(* Logix 5000 project; controller V16_L55_Blank vendor 1 type 14 code 51 rev 16.2; software revision 16.04; part 4 of 5 *)
(* AOI69EAFCMeterLinearGas, continued *)

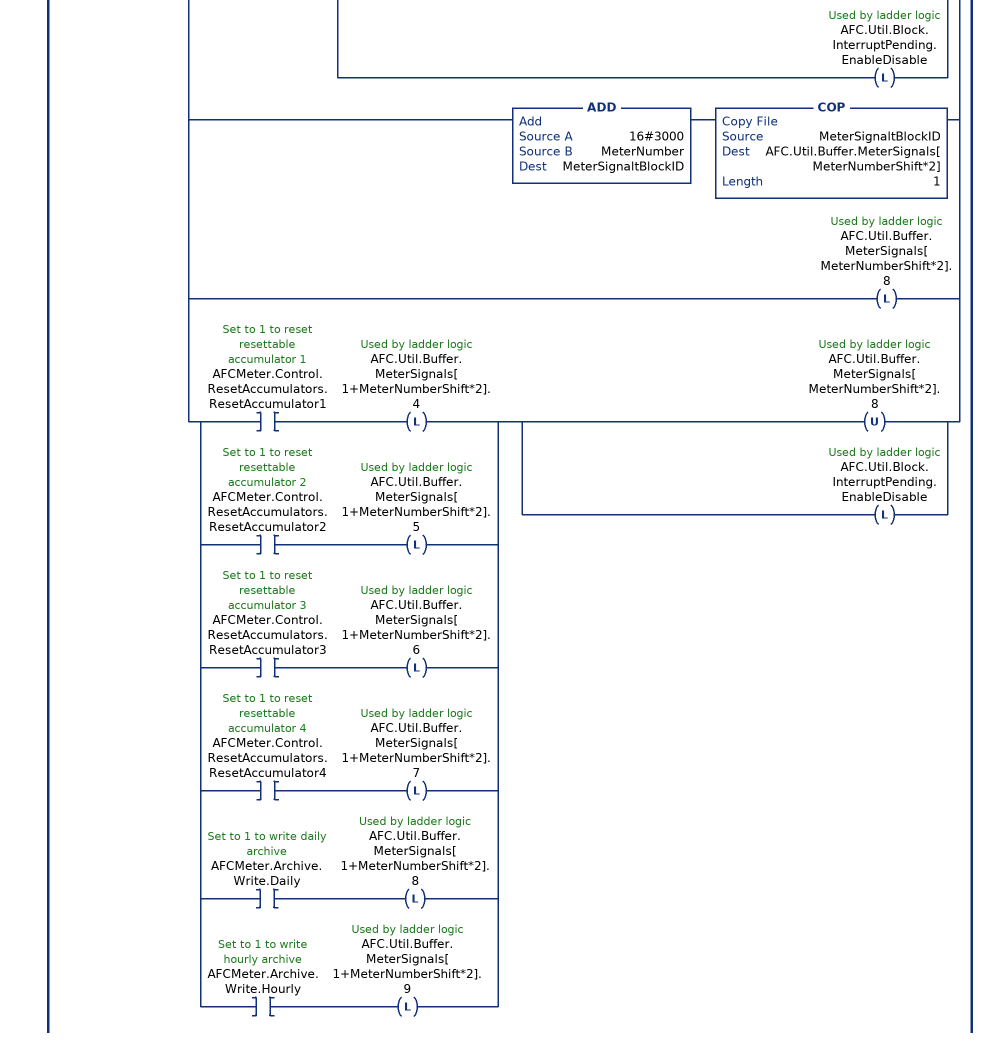
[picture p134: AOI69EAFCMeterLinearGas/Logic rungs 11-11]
   // Meter Enable.
   // Meter Disable.
   // Stream Select.
   // Stream Enable.
   // Stream Disable.
   // Set pending bit if not set this interrupt cycle.
   11: XIO(AFC.Util.Block.InterruptComplete.EnableDisable)[LIM(1,AFCMeter.Control.Stream.Selected,16) CPT(StreamEnableBitPosition,2**(AFCMeter.Control.Stream.Selected-1)) ,[XIC(AFCMeter.Control.Meter.Enable) MVM(16#FFFF,MeterNumberBitPostition,AFC.Util.Buffer.MeterEnableDisable[1]) MVM(16#0000,MeterNumberBitPostition,AFC.Util.Buffer.MeterEnableDisable[3]) ,XIC(AFCMeter.Control.Meter.Disable) MVM(16#FFFF,MeterNumberBitPostition,AFC.Util.Buffer.MeterEnableDisable[3]) MVM(16#0000,MeterNumberBitPostition,AFC.Util.Buffer.MeterEnableDisable[1]) ] OTL(AFC.Util.Block.InterruptPending.EnableDisable) ,[ADD(16#CC00,MeterNumber,StreamEnableBlockID) COP(StreamEnableBlockID,AFC.Util.Buffer.StreamEnable[MeterNumberShift*3],1) ,XIO(AFCMeter.Control.Stream.EnableSelected) OTL(AFC.Util.Buffer.StreamEnable[MeterNumberShift*3].8) ,XIC(AFCMeter.Control.Stream.EnableSelected) [OTU(AFC.Util.Buffer.StreamEnable[MeterNumberShift*3].8) ,COP(StreamEnableBitPosition,AFC.Util.Buffer.StreamEnable[1+MeterNumberShift*3],1) ,OTL(AFC.Util.Block.InterruptPending.EnableDisable) ] ] ,[ADD(16#C800,MeterNumber,StreamDisableBlockID) COP(StreamDisableBlockID,AFC.Util.Buffer.StreamDisable[MeterNumberShift*3],1) ,XIO(AFCMeter.Control.Stream.DisableSelected) OTL(AFC.Util.Buffer.StreamDisable[MeterNumberShift*3].8) ,XIC(AFCMeter.Control.Stream.DisableSelected) [OTU(AFC.Util.Buffer.StreamDisable[MeterNumberShift*3].8) ,COP(StreamEnableBitPosition,AFC.Util.Buffer.StreamDisable[1+MeterNumberShift*3],1) ,OTL(AFC.Util.Block.InterruptPending.EnableDisable) ] ] ,[ADD(16#3C00,MeterNumber,StreamSelectBlockID) COP(StreamSelectBlockID,AFC.Util.Buffer.StreamSelect[MeterNumberShift*2],1) ,XIO(AFCMeter.Control.Stream.SetSelectedToActive) OTL(AFC.Util.Buffer.StreamSelect[MeterNumberShift*2].8) ,XIC(AFCMeter.Control.Stream.SetSelectedToActive) [OTU(AFC.Util.Buffer.StreamSelect[MeterNumberShift*2].8) ,MOV(AFCMeter.Control.Stream.Selected,AFC.Util.Buffer.StreamSelect[1+MeterNumberShift*2]) ,OTL(AFC.Util.Block.InterruptPending.EnableDisable) ] ] ,[ADD(16#3000,MeterNumber,MeterSignaltBlockID) COP(MeterSignaltBlockID,AFC.Util.Buffer.MeterSignals[MeterNumberShift*2],1) ,OTL(AFC.Util.Buffer.MeterSignals[MeterNumberShift*2].8) ,[XIC(AFCMeter.Control.ResetAccumulators.ResetAccumulator1) OTL(AFC.Util.Buffer.MeterSignals[1+MeterNumberShift*2].4) ,XIC(AFCMeter.Control.ResetAccumulators.ResetAccumulator2) OTL(AFC.Util.Buffer.MeterSignals[1+MeterNumberShift*2].5) ,XIC(AFCMeter.Control.ResetAccumulators.ResetAccumulator3) OTL(AFC.Util.Buffer.MeterSignals[1+MeterNumberShift*2].6) ,XIC(AFCMeter.Control.ResetAccumulators.ResetAccumulator4) OTL(AFC.Util.Buffer.MeterSignals[1+MeterNumberShift*2].7) ,XIC(AFCMeter.Archive.Write.Daily) OTL(AFC.Util.Buffer.MeterSignals[1+MeterNumberShift*2].8) ,XIC(AFCMeter.Archive.Write.Hourly) OTL(AFC.Util.Buffer.MeterSignals[1+MeterNumberShift*2].9) ] [OTU(AFC.Util.Buffer.MeterSignals[MeterNumberShift*2].8) ,OTL(AFC.Util.Block.InterruptPending.EnableDisable) ] ] ];
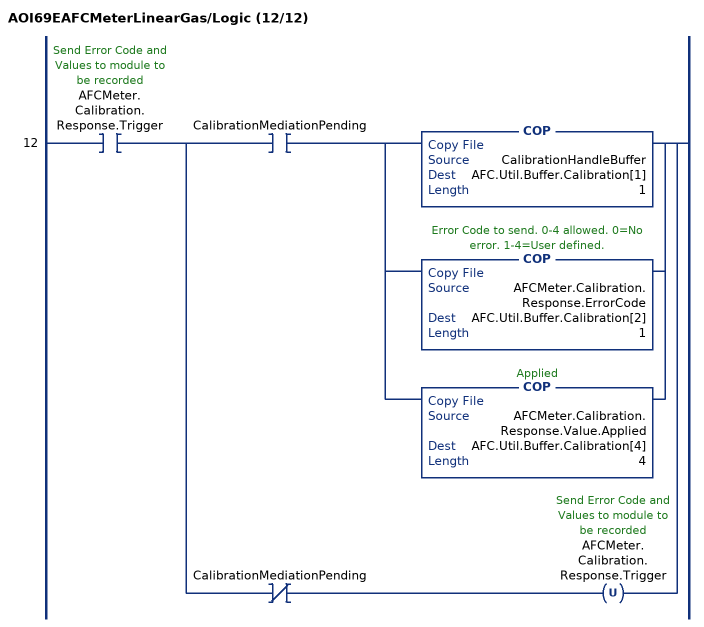
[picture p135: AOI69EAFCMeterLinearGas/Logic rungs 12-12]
   12: XIC(AFCMeter.Calibration.Response.Trigger)[XIC(CalibrationMediationPending) [COP(CalibrationHandleBuffer,AFC.Util.Buffer.Calibration[1],1) ,COP(AFCMeter.Calibration.Response.ErrorCode,AFC.Util.Buffer.Calibration[2],1) ,COP(AFCMeter.Calibration.Response.Value.Applied,AFC.Util.Buffer.Calibration[4],4) ] ,XIO(CalibrationMediationPending) OTU(AFCMeter.Calibration.Response.Trigger) ];
END_ROUTINE

ROUTINE Prescan   (* ladder *)
// Prescan
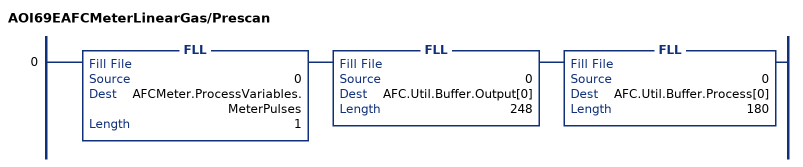
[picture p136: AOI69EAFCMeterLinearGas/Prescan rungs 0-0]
   0: FLL(0,AFCMeter.ProcessVariables.MeterPulses,1)FLL(0,AFC.Util.Buffer.Output[0],248)FLL(0,AFC.Util.Buffer.Process[0],180);
END_ROUTINE
END_ADD_ON_INSTRUCTION

ADD_ON_INSTRUCTION AOI69EAFCMeterLinearLiquid   (* revision 1.5, ExecutePrescan *)
// Add-On instruction for the MVI69E-AFC.
// Linear Liquid Meter.
// Revision note:
// Updated  BackplaneReturn Tag name from ProcessInputs to Standard
// and ComponentAnalysis to Extended
// Help:
// Compatible with version 4.04 of MVI69E-AFC firmware or higher.
// v1.1: Comp Analysis Return fix
// v1.2: Addition of default process input backplane return data mapping.
// v1.3: Changed Prescan FLL instruction length from 240 words to 180 for proccess inputs. This stopped mismatch issue.
// v1.3: Made correlation changes between the Module Archive Default UDTs and the AOI Archive Default UDTs.
// v1.4: Made changes to the ModbusGatewayConfig UDT StartRegister Tag Data Type from INT to DINT.
// v1.5: Updated Tags names AFCMeterXXYYYYYY.BackPlaneReturn.ProcessInputs to
// AFCMeterXXYYYYYY.BackPlaneReturn.Standard and
// AFCMeterXXYYYYYY.BackPlaneReturn.ComponentAnalysis
//  to AFCMeterXXYYYYYY.BackPlaneReturn.Extended.
VAR_IN_OUT
   ConnectionInput : INT[248]; {required}
   AFC : AFCEModuleDef; {required}
   AFCMeter : AFCEMeterLinearLiquid; {required}
END_VAR
VAR_INPUT
   MeterNumber : SINT; {required}   // Meter Number Set to a number between 1 and 12
END_VAR
VAR
   StreamSelectedShift : DINT;
   StreamSelectBuffer : INT;
   EnabledStatusBuffer : INT;
   StreamSelectBlockID : DINT;
   StreamNumberShift : DINT;
   StreamErrorBuffer : DINT;
   StreamEnableBlockID : DINT;
   StreamEnableBitPosition : DINT;
   StreamDisableBlockID : DINT;
   ResetOnce : BOOL;
   ProfileBuffer : SINT[2];
   ProcessInputBlockID : DINT;
   AnalysisGroupBitPosition : INT;
   AnalysisErrorBuffer : INT;
   ProcessAlarmShifter : DINT;
   ProcessAlarmHolder : DINT;
   ProcessAlarmBuffer : DINT;
   MeterSignaltBlockID : DINT;
   MeterNumberShift : DINT;
   MeterNumberBitPostition : DINT;
   Inputbuffer : INT[248];
   CalibrationMeterNumberBuffer : DINT;
   CalibrationMediationPending : BOOL;
   CalibrationInputScalingIndex : DINT;
   CalibrationHandleBuffer : DINT;
   ArchiveStream : DINT;
   ArchiveMeterStatusRaw : DINT;
   ArchiveMeterStatusActiveStream : DINT;
   ArchiveCompleteBitCheck : DINT;
   ArchiveBlockID : DINT;
   AnalysisGroupShift : DINT;
   AnalysisCompleteBitCheck : DINT;
   AnalysisBufferOffset : DINT;
   AFCStopped : BOOL;
   AFCInputDataAvailable : BOOL;
   AnalysisBlockID : DINT;
END_VAR

ROUTINE Logic   (* ladder *)
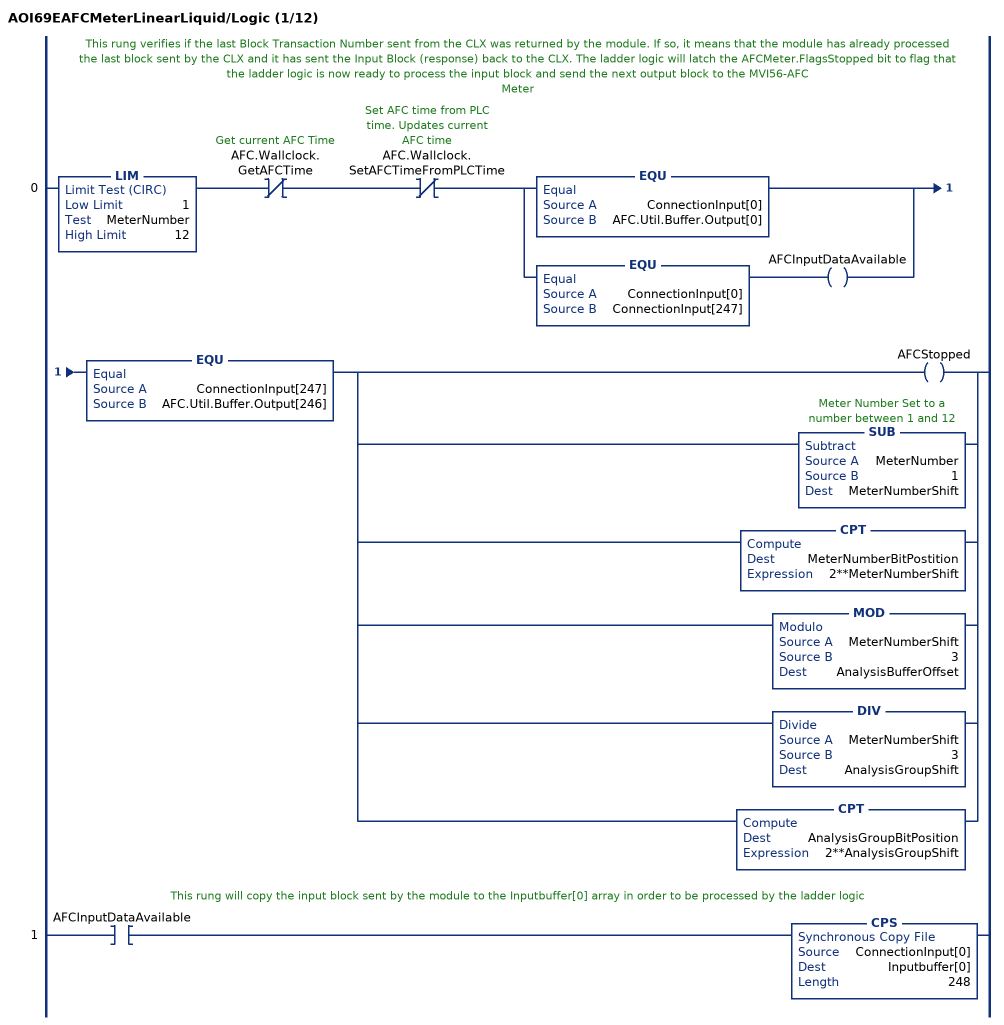
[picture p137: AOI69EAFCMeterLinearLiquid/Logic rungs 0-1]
   // This rung verifies if the last Block Transaction Number sent from the CLX was returned by the module. If so, it means that the module has already processed the last block sent by the CLX and it has sent the Input Block (response) back to the CLX. The ladder logic will latch the AFCMeter.FlagsStopped bit to flag that the ladder logic is now ready to process the input block and send the next output block to the MVI56-AFC
   // Meter
   0: LIM(1,MeterNumber,12)XIO(AFC.Wallclock.GetAFCTime)XIO(AFC.Wallclock.SetAFCTimeFromPLCTime)[EQU(ConnectionInput[0],AFC.Util.Buffer.Output[0]) ,EQU(ConnectionInput[0],ConnectionInput[247]) OTE(AFCInputDataAvailable) ]EQU(ConnectionInput[247],AFC.Util.Buffer.Output[246])[OTE(AFCStopped) ,SUB(MeterNumber,1,MeterNumberShift) ,CPT(MeterNumberBitPostition,2**MeterNumberShift) ,MOD(MeterNumberShift,3,AnalysisBufferOffset) ,DIV(MeterNumberShift,3,AnalysisGroupShift) ,CPT(AnalysisGroupBitPosition,2**AnalysisGroupShift) ];
   // This rung will copy the input block sent by the module to the Inputbuffer[0] array in order to be processed by the ladder logic
   1: XIC(AFCInputDataAvailable)CPS(ConnectionInput[0],Inputbuffer[0],248);
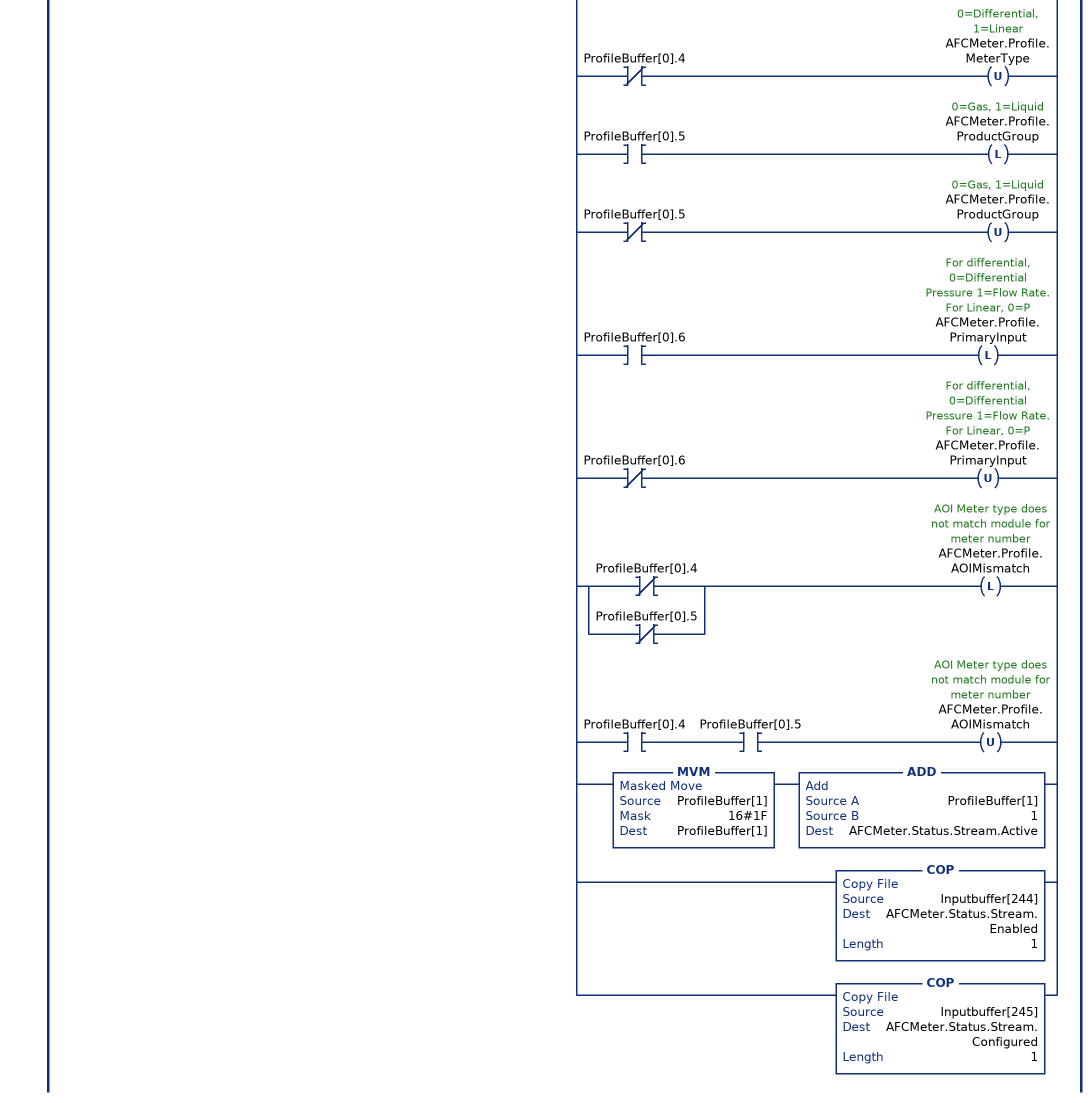
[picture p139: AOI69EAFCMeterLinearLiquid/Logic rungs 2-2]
   // Read process input backplane return and
   // meter profile (when block ID matches meter number).
   2: XIC(AFCInputDataAvailable)LIM(1,Inputbuffer[0],12)[COP(Inputbuffer[3+MeterNumberShift*15],AFCMeter.BackPlaneReturn.StandardRaw[0],14) ,COP(AFCMeter.BackPlaneReturn.StandardRaw[0],AFCMeter.BackPlaneReturn.StandardDefault,1) ,COP(Inputbuffer[246],AFC.SiteStatus,1) ,EQU(Inputbuffer[0],MeterNumber) [COP(Inputbuffer[243],ProfileBuffer[0],2) ,[XIC(ProfileBuffer[0].0) OTL(AFCMeter.Status.Meter.EnableAlarm) ,XIO(ProfileBuffer[0].0) OTU(AFCMeter.Status.Meter.EnableAlarm) ] ,[XIC(ProfileBuffer[0].1) OTL(AFCMeter.Status.Meter.Enabled) ,XIO(ProfileBuffer[0].1) OTU(AFCMeter.Status.Meter.Enabled) ] ,[[XIC(ProfileBuffer[0].4) OTL(AFCMeter.Profile.MeterType) ,XIO(ProfileBuffer[0].4) OTU(AFCMeter.Profile.MeterType) ] ,[XIC(ProfileBuffer[0].5) OTL(AFCMeter.Profile.ProductGroup) ,XIO(ProfileBuffer[0].5) OTU(AFCMeter.Profile.ProductGroup) ] ,[XIC(ProfileBuffer[0].6) OTL(AFCMeter.Profile.PrimaryInput) ,XIO(ProfileBuffer[0].6) OTU(AFCMeter.Profile.PrimaryInput) ] ] ,[[XIO(ProfileBuffer[0].4) ,XIO(ProfileBuffer[0].5) ] OTL(AFCMeter.Profile.AOIMismatch) ,XIC(ProfileBuffer[0].4) XIC(ProfileBuffer[0].5) OTU(AFCMeter.Profile.AOIMismatch) ] ,MVM(ProfileBuffer[1],16#1F,ProfileBuffer[1]) ADD(ProfileBuffer[1],1,AFCMeter.Status.Stream.Active) ,COP(Inputbuffer[244],AFCMeter.Status.Stream.Enabled,1) ,COP(Inputbuffer[245],AFCMeter.Status.Stream.Configured,1) ] ];
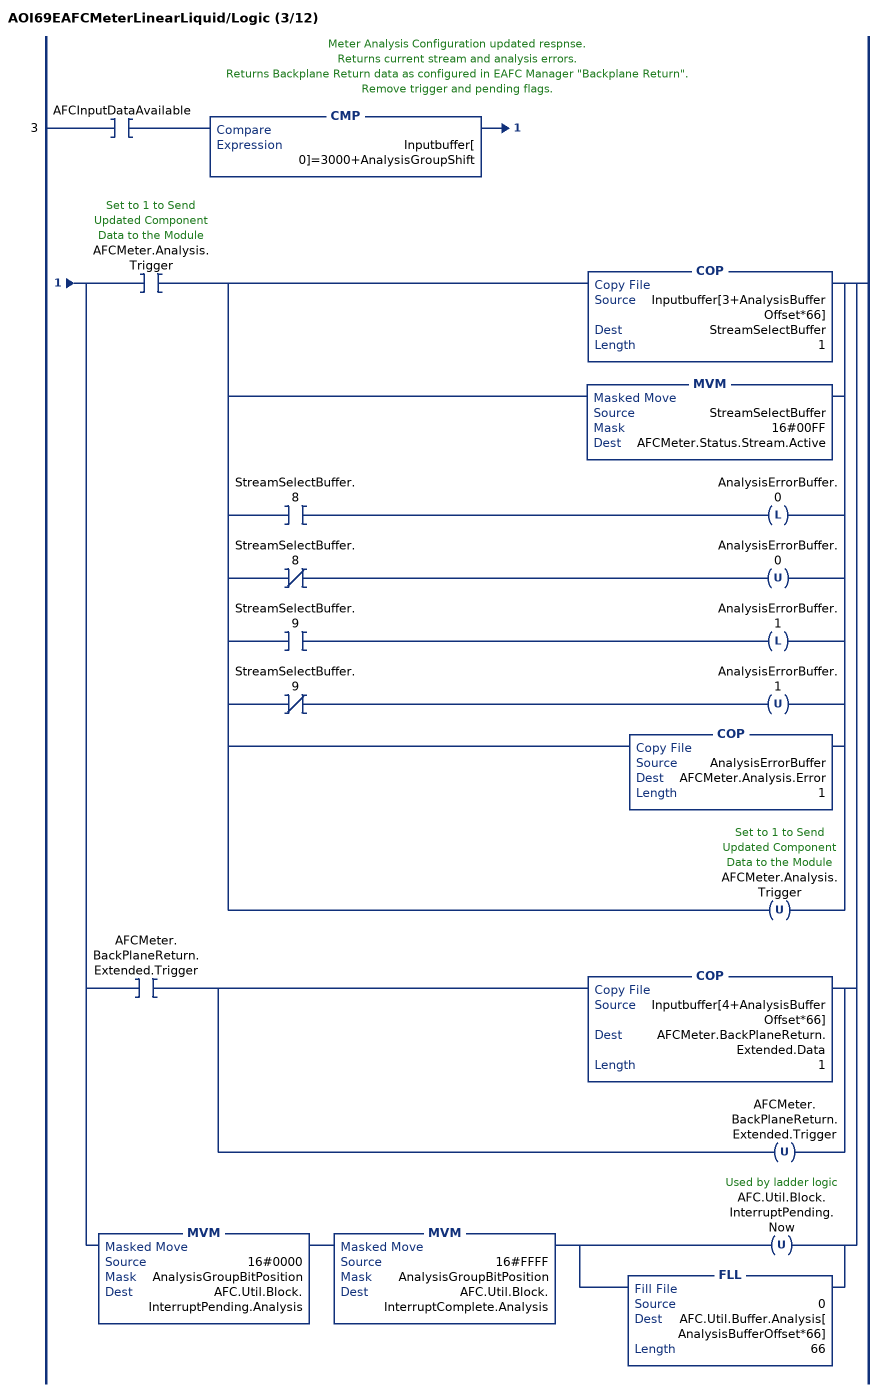
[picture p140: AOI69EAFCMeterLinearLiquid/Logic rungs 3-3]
   // Meter Analysis Configuration updated respnse.
   // Returns current stream and analysis errors.
   // Returns Backplane Return data as configured in EAFC Manager "Backplane Return".
   // Remove trigger and pending flags.
   3: XIC(AFCInputDataAvailable)CMP(Inputbuffer[0]=3000+AnalysisGroupShift)[XIC(AFCMeter.Analysis.Trigger) [COP(Inputbuffer[3+AnalysisBufferOffset*66],StreamSelectBuffer,1) ,MVM(StreamSelectBuffer,16#00FF,AFCMeter.Status.Stream.Active) ,[XIC(StreamSelectBuffer.8) OTL(AnalysisErrorBuffer.0) ,XIO(StreamSelectBuffer.8) OTU(AnalysisErrorBuffer.0) ] ,[XIC(StreamSelectBuffer.9) OTL(AnalysisErrorBuffer.1) ,XIO(StreamSelectBuffer.9) OTU(AnalysisErrorBuffer.1) ] ,COP(AnalysisErrorBuffer,AFCMeter.Analysis.Error,1) ,OTU(AFCMeter.Analysis.Trigger) ] ,XIC(AFCMeter.BackPlaneReturn.Extended.Trigger) [COP(Inputbuffer[4+AnalysisBufferOffset*66],AFCMeter.BackPlaneReturn.Extended.Data,1) ,OTU(AFCMeter.BackPlaneReturn.Extended.Trigger) ] ,MVM(16#0000,AnalysisGroupBitPosition,AFC.Util.Block.InterruptPending.Analysis) MVM(16#FFFF,AnalysisGroupBitPosition,AFC.Util.Block.InterruptComplete.Analysis) [OTU(AFC.Util.Block.InterruptPending.Now) ,FLL(0,AFC.Util.Buffer.Analysis[AnalysisBufferOffset*66],66) ] ];
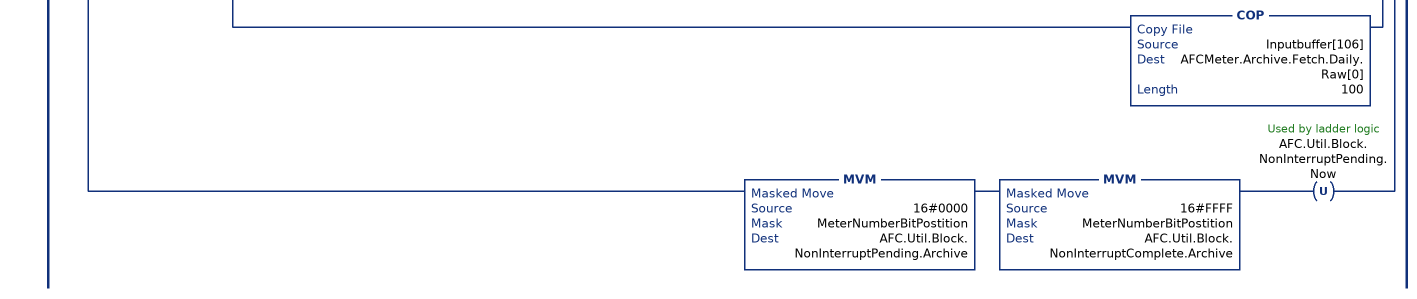
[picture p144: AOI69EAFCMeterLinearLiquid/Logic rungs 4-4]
   // Archive Fetch to default and raw UDT's.
   // Get archive alarms.
   // Remove trigger and pending flags.
   4: XIC(AFCInputDataAvailable)CMP(Inputbuffer[0]=6000+MeterNumberShift)[XIC(AFCMeter.Archive.Fetch.Hourly.Trigger) [OTU(AFCMeter.Archive.Fetch.Hourly.Trigger) ,[[XIC(Inputbuffer[3].0) OTL(AFCMeter.Archive.Fetch.Hourly.Error.ArchiveSelectionInvalid) ,XIO(Inputbuffer[3].0) OTU(AFCMeter.Archive.Fetch.Hourly.Error.ArchiveSelectionInvalid) ] ,[XIC(Inputbuffer[3].1) OTL(AFCMeter.Archive.Fetch.Hourly.Error.AgeOutsideSize) ,XIO(Inputbuffer[3].1) OTU(AFCMeter.Archive.Fetch.Hourly.Error.AgeOutsideSize) ] ,[XIC(Inputbuffer[3].2) OTL(AFCMeter.Archive.Fetch.Hourly.Error.ArchiveNeverWritten) ,XIO(Inputbuffer[3].2) OTU(AFCMeter.Archive.Fetch.Hourly.Error.ArchiveNeverWritten) ] ] ,COP(Inputbuffer[4],AFCMeter.Archive.Fetch.Hourly.Default.ClosingTimestamp,1) ,COP(Inputbuffer[6],AFCMeter.Archive.Fetch.Hourly.Default.CumulativeActiveStreams,1) ,COP(Inputbuffer[7],ArchiveMeterStatusActiveStream,1) [MVM(ArchiveMeterStatusActiveStream,16#0000000F,ArchiveStream) ADD(ArchiveStream,1,AFCMeter.Archive.Fetch.Hourly.Default.CurrentActiveStream) ,MVM(ArchiveMeterStatusActiveStream,16#0000FF00,ArchiveMeterStatusRaw) DIV(ArchiveMeterStatusRaw,256,ArchiveMeterStatusRaw) COP(ArchiveMeterStatusRaw,AFCMeter.Archive.Fetch.Hourly.Default.MeterStatus,1) ] ,COP(Inputbuffer[8],AFCMeter.Archive.Fetch.Hourly.Default.FlowingPeriod,48) ,COP(Inputbuffer[4],AFCMeter.Archive.Fetch.Hourly.Raw[0],100) ] ,XIC(AFCMeter.Archive.Fetch.Daily.Trigger) [OTU(AFCMeter.Archive.Fetch.Daily.Trigger) ,[[XIC(Inputbuffer[105].0) OTL(AFCMeter.Archive.Fetch.Daily.Error.ArchiveSelectionInvalid) ,XIO(Inputbuffer[105].0) OTU(AFCMeter.Archive.Fetch.Daily.Error.ArchiveSelectionInvalid) ] ,[XIC(Inputbuffer[105].1) OTL(AFCMeter.Archive.Fetch.Daily.Error.AgeOutsideSize) ,XIO(Inputbuffer[105].1) OTU(AFCMeter.Archive.Fetch.Daily.Error.AgeOutsideSize) ] ,[XIC(Inputbuffer[105].2) OTL(AFCMeter.Archive.Fetch.Daily.Error.ArchiveNeverWritten) ,XIO(Inputbuffer[105].2) OTU(AFCMeter.Archive.Fetch.Daily.Error.ArchiveNeverWritten) ] ] ,COP(Inputbuffer[106],AFCMeter.Archive.Fetch.Daily.Default.ClosingTimestamp,1) ,COP(Inputbuffer[108],AFCMeter.Archive.Fetch.Daily.Default.CumulativeActiveStreams,1) ,COP(Inputbuffer[109],ArchiveMeterStatusActiveStream,1) [MVM(ArchiveMeterStatusActiveStream,16#0000000F,ArchiveStream) ADD(ArchiveStream,1,AFCMeter.Archive.Fetch.Daily.Default.CurrentActiveStream) ,MVM(ArchiveMeterStatusActiveStream,16#0000FF00,ArchiveMeterStatusRaw) DIV(ArchiveMeterStatusRaw,256,ArchiveMeterStatusRaw) COP(ArchiveMeterStatusRaw,AFCMeter.Archive.Fetch.Daily.Default.MeterStatus,1) ] ,COP(Inputbuffer[110],AFCMeter.Archive.Fetch.Daily.Default.FlowingPeriod,48) ,COP(Inputbuffer[106],AFCMeter.Archive.Fetch.Daily.Raw[0],100) ] ,MVM(16#0000,MeterNumberBitPostition,AFC.Util.Block.NonInterruptPending.Archive) MVM(16#FFFF,MeterNumberBitPostition,AFC.Util.Block.NonInterruptComplete.Archive) OTU(AFC.Util.Block.NonInterruptPending.Now) ];
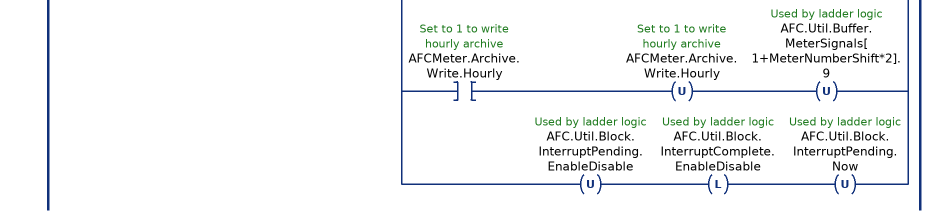
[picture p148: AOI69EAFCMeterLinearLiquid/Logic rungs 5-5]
   // Meter status and stream status.
   // Remove trigger and pending flags.
   5: XIC(AFCInputDataAvailable)EQU(Inputbuffer[0],7000)[[MVM(Inputbuffer[3],MeterNumberBitPostition,EnabledStatusBuffer) ,[NEQ(EnabledStatusBuffer,0) OTL(AFCMeter.Status.Meter.Enabled) ,EQU(EnabledStatusBuffer,0) OTU(AFCMeter.Status.Meter.Enabled) ] ,OTU(AFCMeter.Control.Meter.Enable) MVM(16#0000,MeterNumberBitPostition,AFC.Util.Buffer.MeterEnableDisable[1]) ,OTU(AFCMeter.Control.Meter.Disable) MVM(16#0000,MeterNumberBitPostition,AFC.Util.Buffer.MeterEnableDisable[3]) ] ,[XIC(AFCMeter.Control.Stream.EnableSelected) [COP(Inputbuffer[7+MeterNumberShift*3],AFCMeter.Status.Stream.Enabled,1) ,COP(Inputbuffer[8+MeterNumberShift*3],AFCMeter.Status.Stream.Configured,1) ,OTU(AFCMeter.Control.Stream.EnableSelected) OTU(AFCMeter.Control.Stream.DisableSelected) ] ,XIC(AFCMeter.Control.Stream.DisableSelected) [COP(Inputbuffer[55+MeterNumberShift*3],AFCMeter.Status.Stream.Enabled,1) ,COP(Inputbuffer[56+MeterNumberShift*3],AFCMeter.Status.Stream.Configured,1) ,OTU(AFCMeter.Control.Stream.EnableSelected) OTU(AFCMeter.Control.Stream.DisableSelected) ] ] ,[OTU(AFCMeter.Control.Stream.SetSelectedToActive) ,COP(Inputbuffer[103+MeterNumberShift*2],StreamSelectBuffer,1) ,[XIC(StreamSelectBuffer.8) OTL(StreamErrorBuffer.0) ,XIO(StreamSelectBuffer.8) OTU(StreamErrorBuffer.0) ] ,[XIC(StreamSelectBuffer.9) OTL(StreamErrorBuffer.1) ,XIO(StreamSelectBuffer.9) OTU(StreamErrorBuffer.1) ] ,[XIC(StreamSelectBuffer.10) OTL(StreamErrorBuffer.2) ,XIO(StreamSelectBuffer.10) OTU(StreamErrorBuffer.2) ] ,[XIC(StreamSelectBuffer.11) OTL(StreamErrorBuffer.3) ,XIO(StreamSelectBuffer.11) OTU(StreamErrorBuffer.3) ] ,MVM(StreamSelectBuffer,16#000F,StreamSelectedShift) ADD(StreamSelectedShift,1,AFCMeter.Status.Stream.Active) ,COP(StreamErrorBuffer,AFCMeter.Status.Stream.EnableAlarm,1) ] ,[XIC(AFCMeter.Control.ResetAccumulators.ResetAccumulator1) OTU(AFCMeter.Control.ResetAccumulators.ResetAccumulator1) OTU(AFC.Util.Buffer.MeterSignals[1+MeterNumberShift*2].4) ,XIC(AFCMeter.Control.ResetAccumulators.ResetAccumulator2) OTU(AFCMeter.Control.ResetAccumulators.ResetAccumulator2) OTU(AFC.Util.Buffer.MeterSignals[1+MeterNumberShift*2].5) ,XIC(AFCMeter.Control.ResetAccumulators.ResetAccumulator3) OTU(AFCMeter.Control.ResetAccumulators.ResetAccumulator3) OTU(AFC.Util.Buffer.MeterSignals[1+MeterNumberShift*2].6) ,XIC(AFCMeter.Control.ResetAccumulators.ResetAccumulator4) OTU(AFCMeter.Control.ResetAccumulators.ResetAccumulator4) OTU(AFC.Util.Buffer.MeterSignals[1+MeterNumberShift*2].7) ,XIC(AFCMeter.Archive.Write.Daily) OTU(AFCMeter.Archive.Write.Daily) OTU(AFC.Util.Buffer.MeterSignals[1+MeterNumberShift*2].8) ,XIC(AFCMeter.Archive.Write.Hourly) OTU(AFCMeter.Archive.Write.Hourly) OTU(AFC.Util.Buffer.MeterSignals[1+MeterNumberShift*2].9) ] ,OTU(AFC.Util.Block.InterruptPending.EnableDisable) OTL(AFC.Util.Block.InterruptComplete.EnableDisable) OTU(AFC.Util.Block.InterruptPending.Now) ];
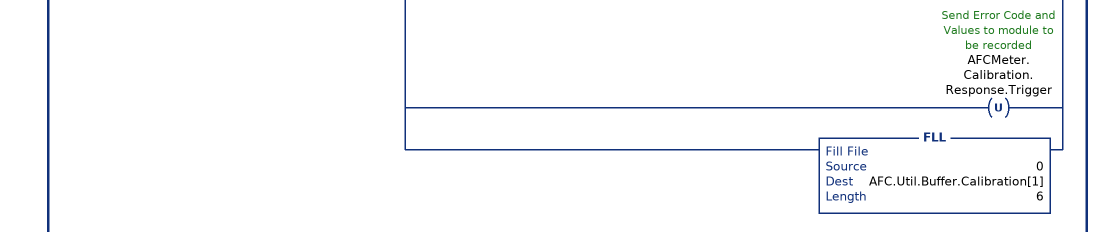
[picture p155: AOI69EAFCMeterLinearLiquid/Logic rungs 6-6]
   // Meter transmitter calibration.
   6: XIC(AFCInputDataAvailable)[EQU(Inputbuffer[0],9000) ,EQU(Inputbuffer[0],9001) ][MVM(Inputbuffer[3],16#0F00,CalibrationMeterNumberBuffer) ,DIV(CalibrationMeterNumberBuffer,16#100,CalibrationMeterNumberBuffer) ]EQU(CalibrationMeterNumberBuffer,MeterNumberShift)XIO(Inputbuffer[3].14)[EQU(Inputbuffer[0],9000) [XIO(CalibrationMediationPending) ADD(AFCMeter.Calibration.Request.Count,1,AFCMeter.Calibration.Request.Count) ,OTL(CalibrationMediationPending) [COP(Inputbuffer[3],CalibrationHandleBuffer,1) ,MVM(CalibrationHandleBuffer,16#000F,CalibrationInputScalingIndex) ] ,[EQU(CalibrationInputScalingIndex,0) [OTL(AFCMeter.Calibration.Request.ProcessVariable.PulseFrequency) ,OTU(AFCMeter.Calibration.Request.ProcessVariable.Temperature) ,OTU(AFCMeter.Calibration.Request.ProcessVariable.Pressure) ,OTU(AFCMeter.Calibration.Request.ProcessVariable.Density) ,OTU(AFCMeter.Calibration.Request.ProcessVariable.WaterContent) ] ,EQU(CalibrationInputScalingIndex,1) [OTL(AFCMeter.Calibration.Request.ProcessVariable.Temperature) ,OTU(AFCMeter.Calibration.Request.ProcessVariable.PulseFrequency) ,OTU(AFCMeter.Calibration.Request.ProcessVariable.Pressure) ,OTU(AFCMeter.Calibration.Request.ProcessVariable.Density) ,OTU(AFCMeter.Calibration.Request.ProcessVariable.WaterContent) ] ,EQU(CalibrationInputScalingIndex,2) [OTL(AFCMeter.Calibration.Request.ProcessVariable.Pressure) ,OTU(AFCMeter.Calibration.Request.ProcessVariable.PulseFrequency) ,OTU(AFCMeter.Calibration.Request.ProcessVariable.Temperature) ,OTU(AFCMeter.Calibration.Request.ProcessVariable.Density) ,OTU(AFCMeter.Calibration.Request.ProcessVariable.WaterContent) ] ,EQU(CalibrationInputScalingIndex,3) [OTL(AFCMeter.Calibration.Request.ProcessVariable.Density) ,OTU(AFCMeter.Calibration.Request.ProcessVariable.PulseFrequency) ,OTU(AFCMeter.Calibration.Request.ProcessVariable.Temperature) ,OTU(AFCMeter.Calibration.Request.ProcessVariable.Pressure) ,OTU(AFCMeter.Calibration.Request.ProcessVariable.WaterContent) ] ,EQU(CalibrationInputScalingIndex,4) [OTL(AFCMeter.Calibration.Request.ProcessVariable.WaterContent) ,OTU(AFCMeter.Calibration.Request.ProcessVariable.PulseFrequency) ,OTU(AFCMeter.Calibration.Request.ProcessVariable.Temperature) ,OTU(AFCMeter.Calibration.Request.ProcessVariable.Pressure) ,OTU(AFCMeter.Calibration.Request.ProcessVariable.Density) ] ] ,[[XIC(Inputbuffer[5].2) [OTL(AFCMeter.Calibration.Request.ActionType.ZeroShift) ,COP(Inputbuffer[6],AFCMeter.Calibration.Request.Value.ZeroShift.Applied,2) ] ,XIO(Inputbuffer[5].2) [OTU(AFCMeter.Calibration.Request.ActionType.ZeroShift) ,FLL(0,AFCMeter.Calibration.Request.Value.ZeroShift.Applied,2) ] ] ,[XIC(Inputbuffer[5].3) [OTL(AFCMeter.Calibration.Request.ActionType.SetZero) ,COP(Inputbuffer[10],AFCMeter.Calibration.Request.Value.SetZero.Applied,2) ] ,XIO(Inputbuffer[5].3) [OTU(AFCMeter.Calibration.Request.ActionType.SetZero) ,FLL(0,AFCMeter.Calibration.Request.Value.SetZero.Applied,2) ] ] ,[XIC(Inputbuffer[5].4) [OTL(AFCMeter.Calibration.Request.ActionType.SetSpan) ,COP(Inputbuffer[14],AFCMeter.Calibration.Request.Value.SetSpan.Applied,2) ] ,XIO(Inputbuffer[5].4) [OTU(AFCMeter.Calibration.Request.ActionType.SetSpan) ,FLL(0,AFCMeter.Calibration.Request.Value.SetSpan.Applied,2) ] ] ,[XIC(Inputbuffer[5].5) [OTL(AFCMeter.Calibration.Request.ActionType.SetMid1) ,COP(Inputbuffer[18],AFCMeter.Calibration.Request.Value.SetMid1.Applied,2) ] ,XIO(Inputbuffer[5].5) [OTU(AFCMeter.Calibration.Request.ActionType.SetMid1) ,FLL(0,AFCMeter.Calibration.Request.Value.SetMid1.Applied,2) ] ] ,[XIC(Inputbuffer[5].6) [OTL(AFCMeter.Calibration.Request.ActionType.SetMid2) ,COP(Inputbuffer[22],AFCMeter.Calibration.Request.Value.SetMid2.Applied,2) ] ,XIO(Inputbuffer[5].6) [OTU(AFCMeter.Calibration.Request.ActionType.SetMid2) ,FLL(0,AFCMeter.Calibration.Request.Value.SetMid2.Applied,2) ] ] ,[XIC(Inputbuffer[5].7) [OTL(AFCMeter.Calibration.Request.ActionType.SetMid3) ,COP(Inputbuffer[26],AFCMeter.Calibration.Request.Value.SetMid3.Applied,2) ] ,XIO(Inputbuffer[5].7) [OTU(AFCMeter.Calibration.Request.ActionType.SetMid3) ,FLL(0,AFCMeter.Calibration.Request.Value.SetMid3.Applied,2) ] ] ] ] ,EQU(Inputbuffer[0],9001) [XIC(AFCMeter.Calibration.Response.Trigger) ADD(AFCMeter.Calibration.Response.Count,1,AFCMeter.Calibration.Response.Count) ,OTU(AFCMeter.Calibration.Response.Trigger) ,FLL(0,AFC.Util.Buffer.Calibration[1],6) ] ];
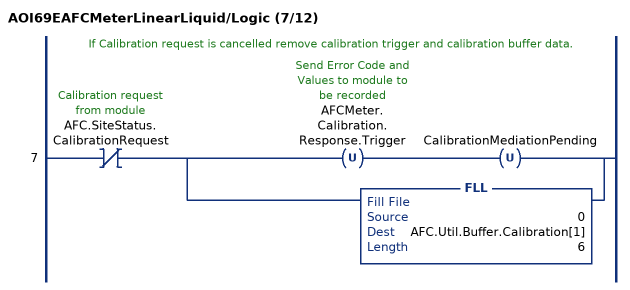
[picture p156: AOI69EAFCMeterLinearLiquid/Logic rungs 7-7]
   // If Calibration request is cancelled remove calibration trigger and calibration buffer data.
   7: XIO(AFC.SiteStatus.CalibrationRequest)[OTU(AFCMeter.Calibration.Response.Trigger) OTU(CalibrationMediationPending) ,FLL(0,AFC.Util.Buffer.Calibration[1],6) ];
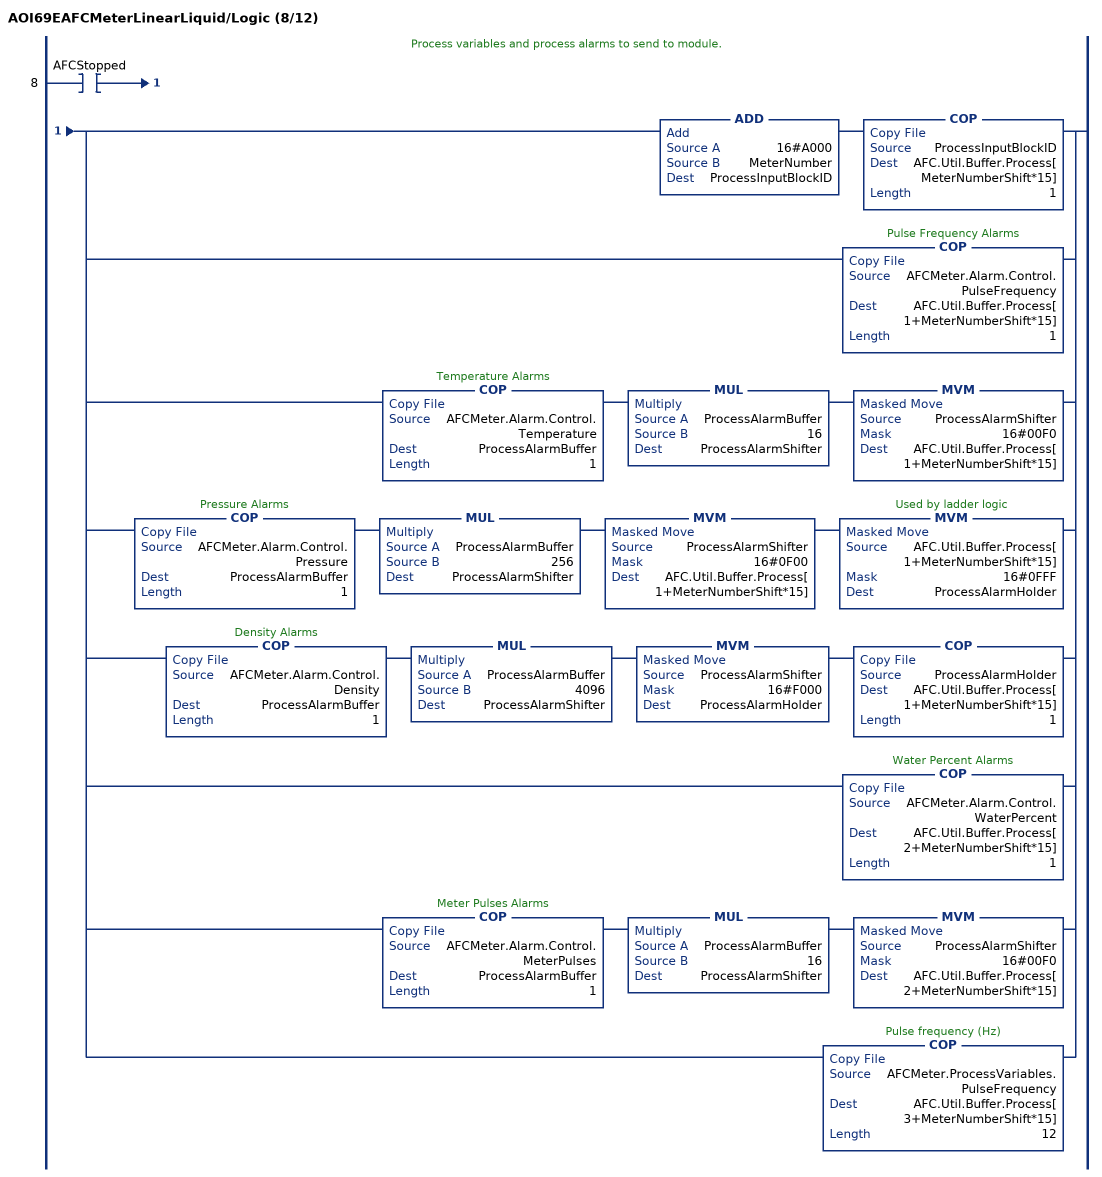
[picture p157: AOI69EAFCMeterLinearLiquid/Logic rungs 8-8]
   // Process variables and process alarms to send to module.
   8: XIC(AFCStopped)[ADD(16#A000,MeterNumber,ProcessInputBlockID) COP(ProcessInputBlockID,AFC.Util.Buffer.Process[MeterNumberShift*15],1) ,COP(AFCMeter.Alarm.Control.PulseFrequency,AFC.Util.Buffer.Process[1+MeterNumberShift*15],1) ,COP(AFCMeter.Alarm.Control.Temperature,ProcessAlarmBuffer,1) MUL(ProcessAlarmBuffer,16,ProcessAlarmShifter) MVM(ProcessAlarmShifter,16#00F0,AFC.Util.Buffer.Process[1+MeterNumberShift*15]) ,COP(AFCMeter.Alarm.Control.Pressure,ProcessAlarmBuffer,1) MUL(ProcessAlarmBuffer,256,ProcessAlarmShifter) MVM(ProcessAlarmShifter,16#0F00,AFC.Util.Buffer.Process[1+MeterNumberShift*15]) MVM(AFC.Util.Buffer.Process[1+MeterNumberShift*15],16#0FFF,ProcessAlarmHolder) ,COP(AFCMeter.Alarm.Control.Density,ProcessAlarmBuffer,1) MUL(ProcessAlarmBuffer,4096,ProcessAlarmShifter) MVM(ProcessAlarmShifter,16#F000,ProcessAlarmHolder) COP(ProcessAlarmHolder,AFC.Util.Buffer.Process[1+MeterNumberShift*15],1) ,COP(AFCMeter.Alarm.Control.WaterPercent,AFC.Util.Buffer.Process[2+MeterNumberShift*15],1) ,COP(AFCMeter.Alarm.Control.MeterPulses,ProcessAlarmBuffer,1) MUL(ProcessAlarmBuffer,16,ProcessAlarmShifter) MVM(ProcessAlarmShifter,16#00F0,AFC.Util.Buffer.Process[2+MeterNumberShift*15]) ,COP(AFCMeter.ProcessVariables.PulseFrequency,AFC.Util.Buffer.Process[3+MeterNumberShift*15],12) ];
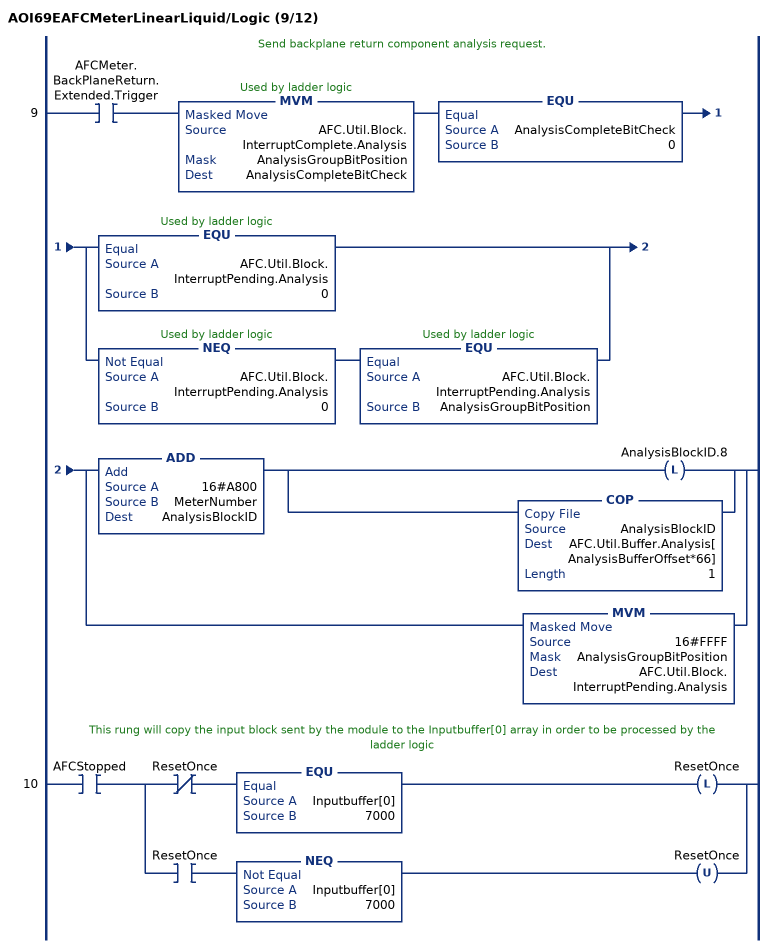
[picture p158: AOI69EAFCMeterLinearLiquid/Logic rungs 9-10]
   // Send backplane return component analysis request.
   9: XIC(AFCMeter.BackPlaneReturn.Extended.Trigger)MVM(AFC.Util.Block.InterruptComplete.Analysis,AnalysisGroupBitPosition,AnalysisCompleteBitCheck)EQU(AnalysisCompleteBitCheck,0)[EQU(AFC.Util.Block.InterruptPending.Analysis,0) ,NEQ(AFC.Util.Block.InterruptPending.Analysis,0) EQU(AFC.Util.Block.InterruptPending.Analysis,AnalysisGroupBitPosition) ][ADD(16#A800,MeterNumber,AnalysisBlockID) [OTL(AnalysisBlockID.8) ,COP(AnalysisBlockID,AFC.Util.Buffer.Analysis[AnalysisBufferOffset*66],1) ] ,MVM(16#FFFF,AnalysisGroupBitPosition,AFC.Util.Block.InterruptPending.Analysis) ];
   // This rung will copy the input block sent by the module to the Inputbuffer[0] array in order to be processed by the ladder logic
   10: XIC(AFCStopped)[XIO(ResetOnce) EQU(Inputbuffer[0],7000) OTL(ResetOnce) ,XIC(ResetOnce) NEQ(Inputbuffer[0],7000) OTU(ResetOnce) ];
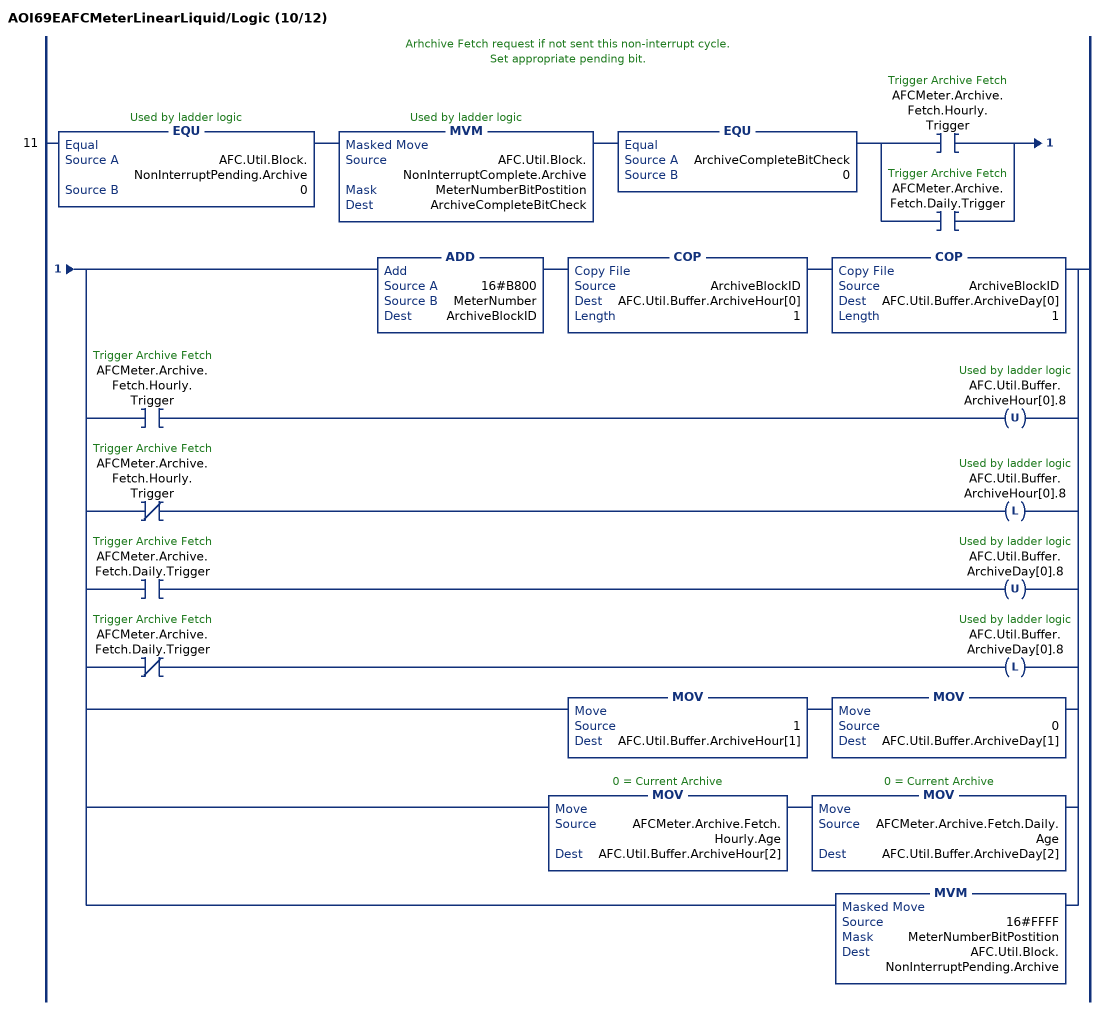
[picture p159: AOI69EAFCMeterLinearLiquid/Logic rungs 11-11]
   // Arhchive Fetch request if not sent this non-interrupt cycle.
   // Set appropriate pending bit.
   11: EQU(AFC.Util.Block.NonInterruptPending.Archive,0)MVM(AFC.Util.Block.NonInterruptComplete.Archive,MeterNumberBitPostition,ArchiveCompleteBitCheck)EQU(ArchiveCompleteBitCheck,0)[XIC(AFCMeter.Archive.Fetch.Hourly.Trigger) ,XIC(AFCMeter.Archive.Fetch.Daily.Trigger) ][ADD(16#B800,MeterNumber,ArchiveBlockID) COP(ArchiveBlockID,AFC.Util.Buffer.ArchiveHour[0],1) COP(ArchiveBlockID,AFC.Util.Buffer.ArchiveDay[0],1) ,[XIC(AFCMeter.Archive.Fetch.Hourly.Trigger) OTU(AFC.Util.Buffer.ArchiveHour[0].8) ,XIO(AFCMeter.Archive.Fetch.Hourly.Trigger) OTL(AFC.Util.Buffer.ArchiveHour[0].8) ] ,[XIC(AFCMeter.Archive.Fetch.Daily.Trigger) OTU(AFC.Util.Buffer.ArchiveDay[0].8) ,XIO(AFCMeter.Archive.Fetch.Daily.Trigger) OTL(AFC.Util.Buffer.ArchiveDay[0].8) ] ,MOV(1,AFC.Util.Buffer.ArchiveHour[1]) MOV(0,AFC.Util.Buffer.ArchiveDay[1]) ,MOV(AFCMeter.Archive.Fetch.Hourly.Age,AFC.Util.Buffer.ArchiveHour[2]) MOV(AFCMeter.Archive.Fetch.Daily.Age,AFC.Util.Buffer.ArchiveDay[2]) ,MVM(16#FFFF,MeterNumberBitPostition,AFC.Util.Block.NonInterruptPending.Archive) ];
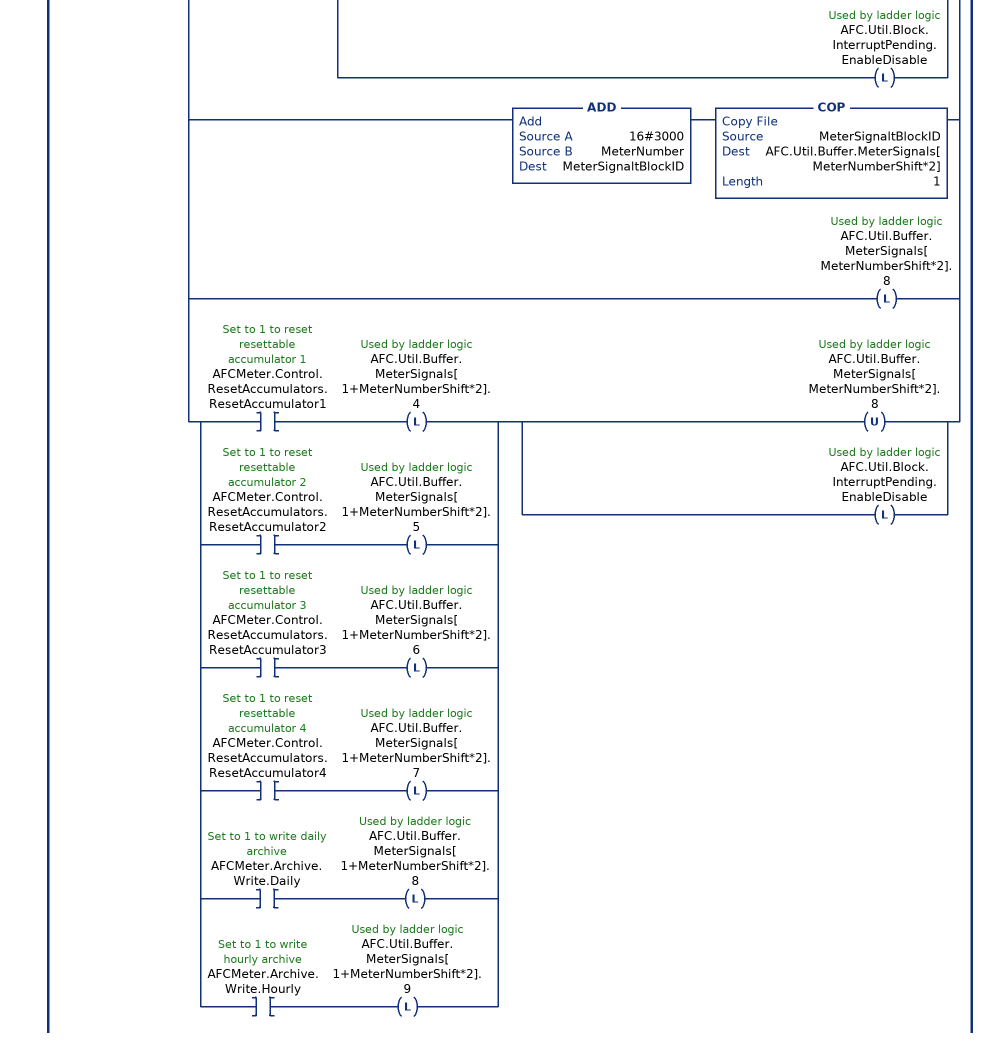
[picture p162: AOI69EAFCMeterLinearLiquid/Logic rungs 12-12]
   // Meter Enable.
   // Meter Disable.
   // Stream Select.
   // Stream Enable.
   // Stream Disable.
   // Set pending bit if not set this interrupt cycle.
   12: XIO(AFC.Util.Block.InterruptComplete.EnableDisable)[LIM(1,AFCMeter.Control.Stream.Selected,12) CPT(StreamEnableBitPosition,2**(AFCMeter.Control.Stream.Selected-1)) ,[XIC(AFCMeter.Control.Meter.Enable) MVM(16#FFFF,MeterNumberBitPostition,AFC.Util.Buffer.MeterEnableDisable[1]) MVM(16#0000,MeterNumberBitPostition,AFC.Util.Buffer.MeterEnableDisable[3]) ,XIC(AFCMeter.Control.Meter.Disable) MVM(16#FFFF,MeterNumberBitPostition,AFC.Util.Buffer.MeterEnableDisable[3]) MVM(16#0000,MeterNumberBitPostition,AFC.Util.Buffer.MeterEnableDisable[1]) ] OTL(AFC.Util.Block.InterruptPending.EnableDisable) ,[ADD(16#CC00,MeterNumber,StreamEnableBlockID) COP(StreamEnableBlockID,AFC.Util.Buffer.StreamEnable[MeterNumberShift*3],1) ,XIO(AFCMeter.Control.Stream.EnableSelected) OTL(AFC.Util.Buffer.StreamEnable[MeterNumberShift*3].8) ,XIC(AFCMeter.Control.Stream.EnableSelected) [OTU(AFC.Util.Buffer.StreamEnable[MeterNumberShift*3].8) ,COP(StreamEnableBitPosition,AFC.Util.Buffer.StreamEnable[1+MeterNumberShift*3],1) ,OTL(AFC.Util.Block.InterruptPending.EnableDisable) ] ] ,[ADD(16#C800,MeterNumber,StreamDisableBlockID) COP(StreamDisableBlockID,AFC.Util.Buffer.StreamDisable[MeterNumberShift*3],1) ,XIO(AFCMeter.Control.Stream.DisableSelected) OTL(AFC.Util.Buffer.StreamDisable[MeterNumberShift*3].8) ,XIC(AFCMeter.Control.Stream.DisableSelected) [OTU(AFC.Util.Buffer.StreamDisable[MeterNumberShift*3].8) ,COP(StreamEnableBitPosition,AFC.Util.Buffer.StreamDisable[1+MeterNumberShift*3],1) ,OTL(AFC.Util.Block.InterruptPending.EnableDisable) ] ] ,[ADD(16#3C00,MeterNumber,StreamSelectBlockID) COP(StreamSelectBlockID,AFC.Util.Buffer.StreamSelect[MeterNumberShift*2],1) ,XIO(AFCMeter.Control.Stream.SetSelectedToActive) OTL(AFC.Util.Buffer.StreamSelect[MeterNumberShift*2].8) ,XIC(AFCMeter.Control.Stream.SetSelectedToActive) [OTU(AFC.Util.Buffer.StreamSelect[MeterNumberShift*2].8) ,MOV(AFCMeter.Control.Stream.Selected,AFC.Util.Buffer.StreamSelect[1+MeterNumberShift*2]) ,OTL(AFC.Util.Block.InterruptPending.EnableDisable) ] ] ,[ADD(16#3000,MeterNumber,MeterSignaltBlockID) COP(MeterSignaltBlockID,AFC.Util.Buffer.MeterSignals[MeterNumberShift*2],1) ,OTL(AFC.Util.Buffer.MeterSignals[MeterNumberShift*2].8) ,[XIC(AFCMeter.Control.ResetAccumulators.ResetAccumulator1) OTL(AFC.Util.Buffer.MeterSignals[1+MeterNumberShift*2].4) ,XIC(AFCMeter.Control.ResetAccumulators.ResetAccumulator2) OTL(AFC.Util.Buffer.MeterSignals[1+MeterNumberShift*2].5) ,XIC(AFCMeter.Control.ResetAccumulators.ResetAccumulator3) OTL(AFC.Util.Buffer.MeterSignals[1+MeterNumberShift*2].6) ,XIC(AFCMeter.Control.ResetAccumulators.ResetAccumulator4) OTL(AFC.Util.Buffer.MeterSignals[1+MeterNumberShift*2].7) ,XIC(AFCMeter.Archive.Write.Daily) OTL(AFC.Util.Buffer.MeterSignals[1+MeterNumberShift*2].8) ,XIC(AFCMeter.Archive.Write.Hourly) OTL(AFC.Util.Buffer.MeterSignals[1+MeterNumberShift*2].9) ] [OTU(AFC.Util.Buffer.MeterSignals[MeterNumberShift*2].8) ,OTL(AFC.Util.Block.InterruptPending.EnableDisable) ] ] ];
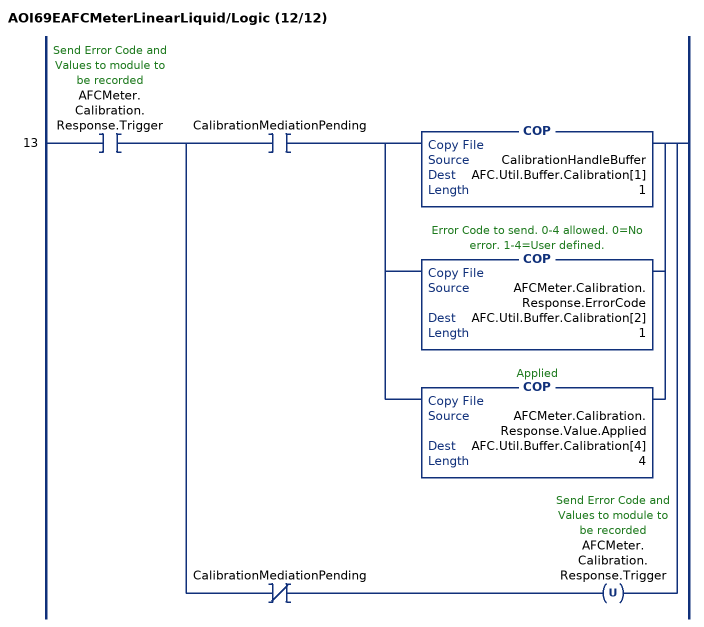
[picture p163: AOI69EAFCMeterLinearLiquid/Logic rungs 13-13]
   13: XIC(AFCMeter.Calibration.Response.Trigger)[XIC(CalibrationMediationPending) [COP(CalibrationHandleBuffer,AFC.Util.Buffer.Calibration[1],1) ,COP(AFCMeter.Calibration.Response.ErrorCode,AFC.Util.Buffer.Calibration[2],1) ,COP(AFCMeter.Calibration.Response.Value.Applied,AFC.Util.Buffer.Calibration[4],4) ] ,XIO(CalibrationMediationPending) OTU(AFCMeter.Calibration.Response.Trigger) ];
END_ROUTINE

ROUTINE Prescan   (* ladder *)
// Prescan
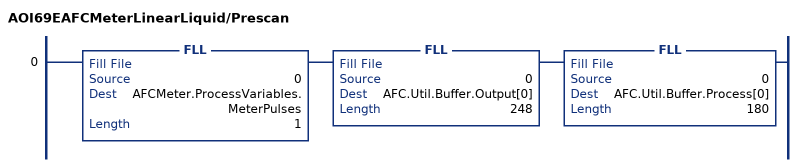
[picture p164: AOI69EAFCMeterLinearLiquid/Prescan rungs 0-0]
   0: FLL(0,AFCMeter.ProcessVariables.MeterPulses,1)FLL(0,AFC.Util.Buffer.Output[0],248)FLL(0,AFC.Util.Buffer.Process[0],180);
END_ROUTINE
END_ADD_ON_INSTRUCTION

ADD_ON_INSTRUCTION AOI69EAFCNetworkConfig   (* revision 1.1, ExecutePrescan *)
// Add-On instruction to update the MVI69E-AFC network settings
// Revision note:
// Made changes to the ModbusGatewayConfig UDT StartRegister Tag Data Type from INT to DINT.
// Help:
// v1.0 Read and write module network configuration.
// v1.1 Made changes to the ModbusGatewayConfig UDT StartRegister Tag Data Type from INT to DINT.
VAR_IN_OUT
   Network : AFCENetwork; {required}
   EAFC : AFCEModuleDef; {required}
END_VAR
VAR
   NetworkBuffer : DINT[2];
   MVMbuffer : INT;
   IndexSizeM1 : DINT;
   IndexSize : DINT;
   Index : DINT;
   ErrorTimer : TIMER;
END_VAR

ROUTINE Logic   (* ladder *)
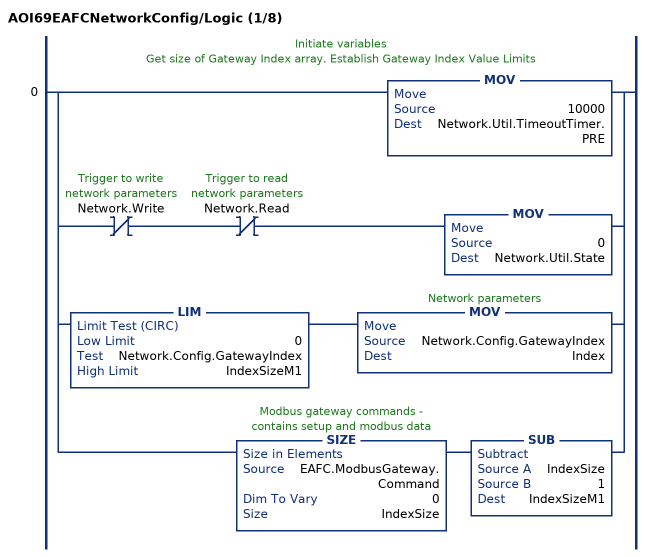
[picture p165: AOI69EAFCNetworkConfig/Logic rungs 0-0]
   // Initiate variables
   // Get size of Gateway Index array. Establish Gateway Index Value Limits
   0: [[MOV(10000,Network.Util.TimeoutTimer.PRE) ,XIO(Network.Write) XIO(Network.Read) MOV(0,Network.Util.State) ] ,LIM(0,Network.Config.GatewayIndex,IndexSizeM1) MOV(Network.Config.GatewayIndex,Index) ,SIZE(EAFC.ModbusGateway.Command,0,IndexSize) SUB(IndexSize,1,IndexSizeM1) ];
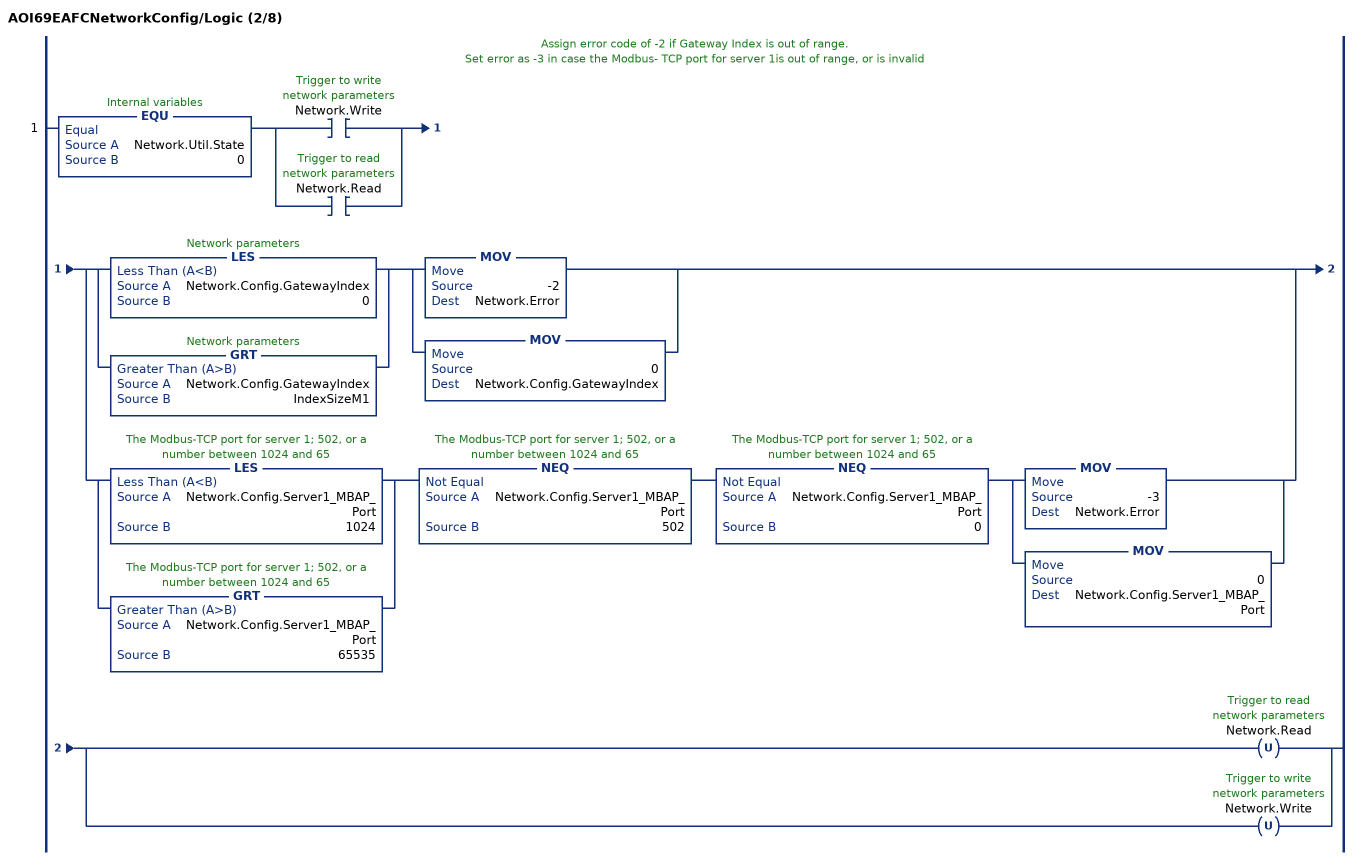
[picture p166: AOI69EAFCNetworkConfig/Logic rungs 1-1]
   // Assign error code of -2 if Gateway Index is out of range.
   // Set error as -3 in case the Modbus- TCP port for server 1is out of range, or is invalid
   1: EQU(Network.Util.State,0)[XIC(Network.Write) ,XIC(Network.Read) ][[LES(Network.Config.GatewayIndex,0) ,GRT(Network.Config.GatewayIndex,IndexSizeM1) ] [MOV(-2,Network.Error) ,MOV(0,Network.Config.GatewayIndex) ] ,[LES(Network.Config.Server1_MBAP_Port,1024) ,GRT(Network.Config.Server1_MBAP_Port,65535) ] NEQ(Network.Config.Server1_MBAP_Port,502) NEQ(Network.Config.Server1_MBAP_Port,0) [MOV(-3,Network.Error) ,MOV(0,Network.Config.Server1_MBAP_Port) ] ][OTU(Network.Read) ,OTU(Network.Write) ];
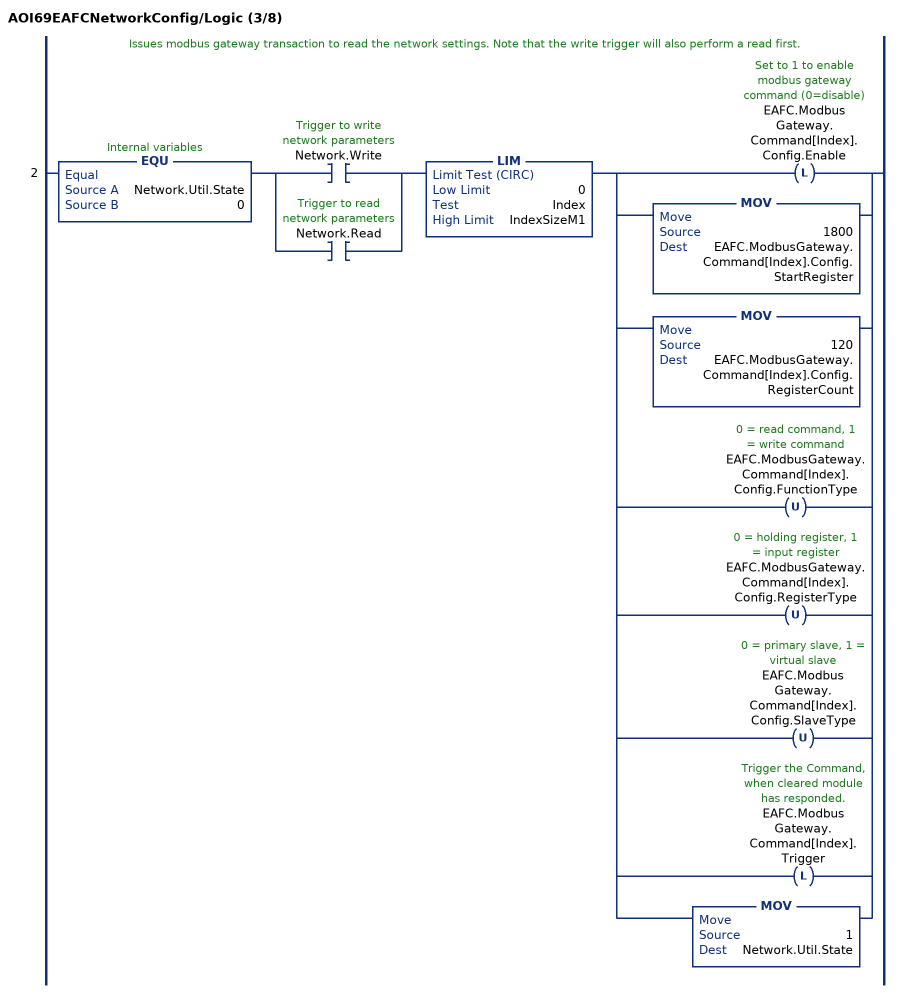
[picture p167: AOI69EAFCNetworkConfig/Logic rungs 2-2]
   // Issues modbus gateway transaction to read the network settings. Note that the write trigger will also perform a read first.
   2: EQU(Network.Util.State,0)[XIC(Network.Write) ,XIC(Network.Read) ]LIM(0,Index,IndexSizeM1)[OTL(EAFC.ModbusGateway.Command[Index].Config.Enable) ,MOV(1800,EAFC.ModbusGateway.Command[Index].Config.StartRegister) ,MOV(120,EAFC.ModbusGateway.Command[Index].Config.RegisterCount) ,OTU(EAFC.ModbusGateway.Command[Index].Config.FunctionType) ,OTU(EAFC.ModbusGateway.Command[Index].Config.RegisterType) ,OTU(EAFC.ModbusGateway.Command[Index].Config.SlaveType) ,OTL(EAFC.ModbusGateway.Command[Index].Trigger) ,MOV(1,Network.Util.State) ];
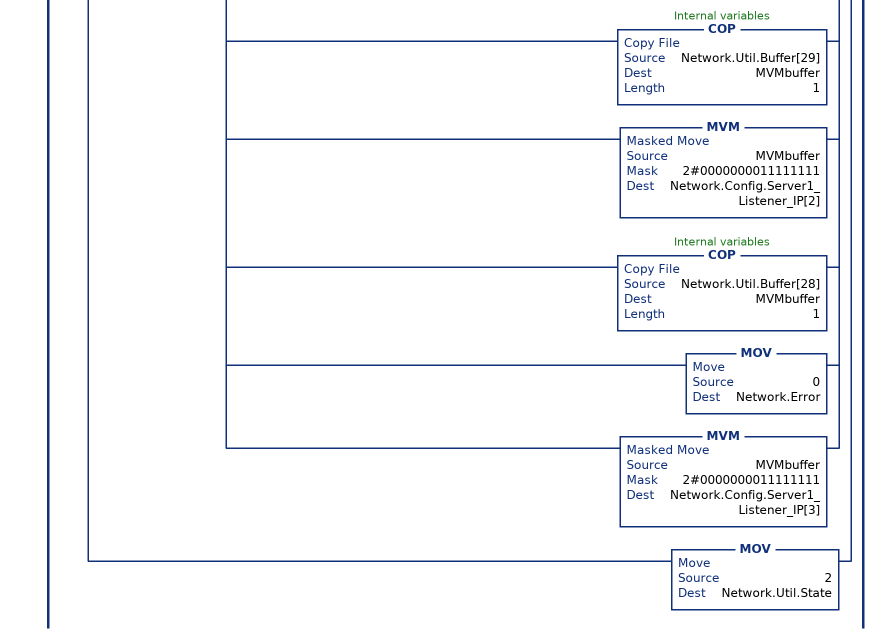
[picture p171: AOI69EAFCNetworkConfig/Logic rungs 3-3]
   // Parses the data received from the module once it detects that the gateway transaction was concluded.
   3: EQU(Network.Util.State,1)[XIC(Network.Write) ,XIC(Network.Read) ]XIO(EAFC.ModbusGateway.Command[Index].Trigger)LIM(0,Index,IndexSizeM1)[COP(EAFC.ModbusGateway.Command[Index].Data[0],Network.Util.Buffer[0],240) ,XIC(Network.Read) [COP(Network.Util.Buffer[3],MVMbuffer,1) ,MVM(MVMbuffer,2#0000000011111111,Network.Config.Physical_Interface_IP[0]) ,COP(Network.Util.Buffer[2],MVMbuffer,1) ,MVM(MVMbuffer,2#0000000011111111,Network.Config.Physical_Interface_IP[1]) ,COP(Network.Util.Buffer[1],MVMbuffer,1) ,MVM(MVMbuffer,2#0000000011111111,Network.Config.Physical_Interface_IP[2]) ,COP(Network.Util.Buffer[0],MVMbuffer,1) ,MVM(MVMbuffer,2#0000000011111111,Network.Config.Physical_Interface_IP[3]) ,MOV(Network.Util.Buffer[4],Network.Config.Physical_Interface_Network_Prefix) ,COP(Network.Util.Buffer[15],MVMbuffer,1) ,MVM(MVMbuffer,2#0000000011111111,Network.Config.Default_Gateway_IP[0]) ,COP(Network.Util.Buffer[14],MVMbuffer,1) ,MVM(MVMbuffer,2#0000000011111111,Network.Config.Default_Gateway_IP[1]) ,COP(Network.Util.Buffer[13],MVMbuffer,1) ,MVM(MVMbuffer,2#0000000011111111,Network.Config.Default_Gateway_IP[2]) ,COP(Network.Util.Buffer[12],MVMbuffer,1) ,MVM(MVMbuffer,2#0000000011111111,Network.Config.Default_Gateway_IP[3]) ,MOV(Network.Util.Buffer[20],Network.Config.Server1_Network_Prefix) ,COP(Network.Util.Buffer[26],NetworkBuffer[0],2) MVM(NetworkBuffer[0],2#00000000000000001111111111111111,Network.Config.Server1_MBAP_Port) ,COP(Network.Util.Buffer[31],MVMbuffer,1) ,MVM(MVMbuffer,2#0000000011111111,Network.Config.Server1_Listener_IP[0]) ,COP(Network.Util.Buffer[30],MVMbuffer,1) ,MVM(MVMbuffer,2#0000000011111111,Network.Config.Server1_Listener_IP[1]) ,COP(Network.Util.Buffer[29],MVMbuffer,1) ,MVM(MVMbuffer,2#0000000011111111,Network.Config.Server1_Listener_IP[2]) ,COP(Network.Util.Buffer[28],MVMbuffer,1) ,MOV(0,Network.Error) ,MVM(MVMbuffer,2#0000000011111111,Network.Config.Server1_Listener_IP[3]) ] ,MOV(2,Network.Util.State) ];
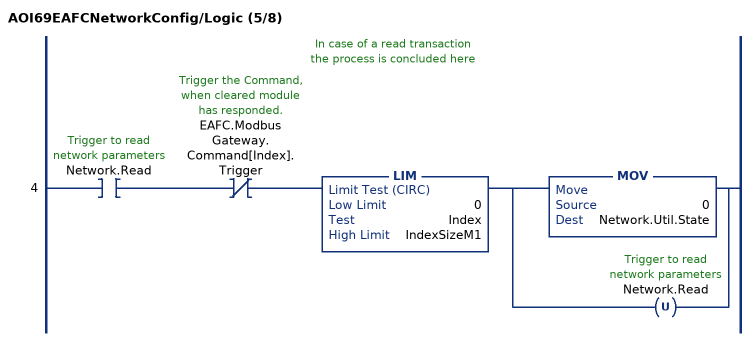
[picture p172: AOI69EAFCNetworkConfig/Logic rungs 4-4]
   // In case of a read transaction
   //  the process is concluded here
   4: XIC(Network.Read)XIO(EAFC.ModbusGateway.Command[Index].Trigger)LIM(0,Index,IndexSizeM1)[MOV(0,Network.Util.State) ,OTU(Network.Read) ];
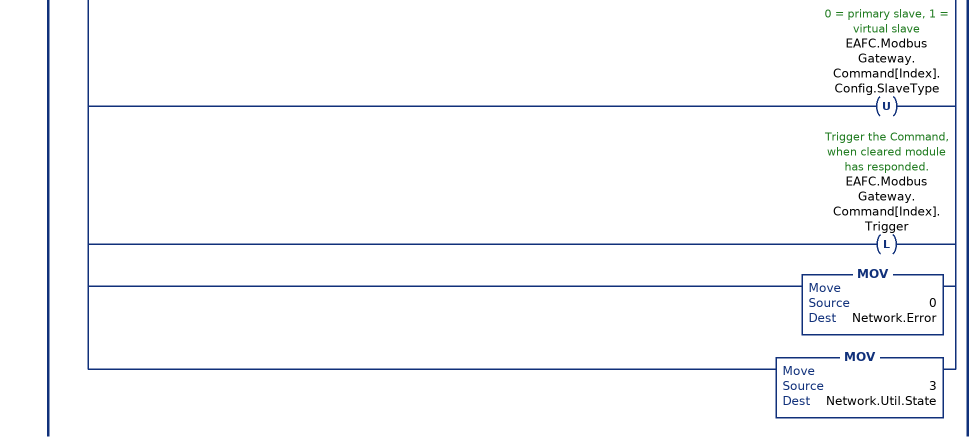
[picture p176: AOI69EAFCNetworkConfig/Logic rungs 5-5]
   // In case this is a write transaction
   //  this rung will update the the specific parameters listed at Network.Config and keep the remaining data the same as read from the module.
   5: EQU(Network.Util.State,2)[LIM(1024,Network.Config.Server1_MBAP_Port,65535) ,EQU(Network.Config.Server1_MBAP_Port,502) ]LIM(0,Index,IndexSizeM1)XIC(Network.Write)[COP(Network.Config.Physical_Interface_IP[0],Network.Util.Buffer[3],1) ,COP(Network.Config.Physical_Interface_IP[1],Network.Util.Buffer[2],1) ,COP(Network.Config.Physical_Interface_IP[2],Network.Util.Buffer[1],1) ,COP(Network.Config.Physical_Interface_IP[3],Network.Util.Buffer[0],1) ,MOV(Network.Config.Physical_Interface_Network_Prefix,Network.Util.Buffer[4]) ,COP(Network.Config.Default_Gateway_IP[0],Network.Util.Buffer[15],1) ,COP(Network.Config.Default_Gateway_IP[1],Network.Util.Buffer[14],1) ,COP(Network.Config.Default_Gateway_IP[2],Network.Util.Buffer[13],1) ,COP(Network.Config.Default_Gateway_IP[3],Network.Util.Buffer[12],1) ,MOV(Network.Config.Server1_Network_Prefix,Network.Util.Buffer[20]) ,COP(Network.Config.Server1_MBAP_Port,Network.Util.Buffer[26],2) ,COP(Network.Config.Server1_Listener_IP[0],Network.Util.Buffer[31],1) ,COP(Network.Config.Server1_Listener_IP[1],Network.Util.Buffer[30],1) ,COP(Network.Config.Server1_Listener_IP[2],Network.Util.Buffer[29],1) ,COP(Network.Config.Server1_Listener_IP[3],Network.Util.Buffer[28],1) ,COP(Network.Util.Buffer[0],EAFC.ModbusGateway.Command[Index].Data[0],120) ,MOV(1800,EAFC.ModbusGateway.Command[Index].Config.StartRegister) ,MOV(120,EAFC.ModbusGateway.Command[Index].Config.RegisterCount) ,OTL(EAFC.ModbusGateway.Command[Index].Config.FunctionType) ,OTU(EAFC.ModbusGateway.Command[Index].Config.RegisterType) ,OTU(EAFC.ModbusGateway.Command[Index].Config.SlaveType) ,OTL(EAFC.ModbusGateway.Command[Index].Trigger) ,MOV(0,Network.Error) ,MOV(3,Network.Util.State) ];
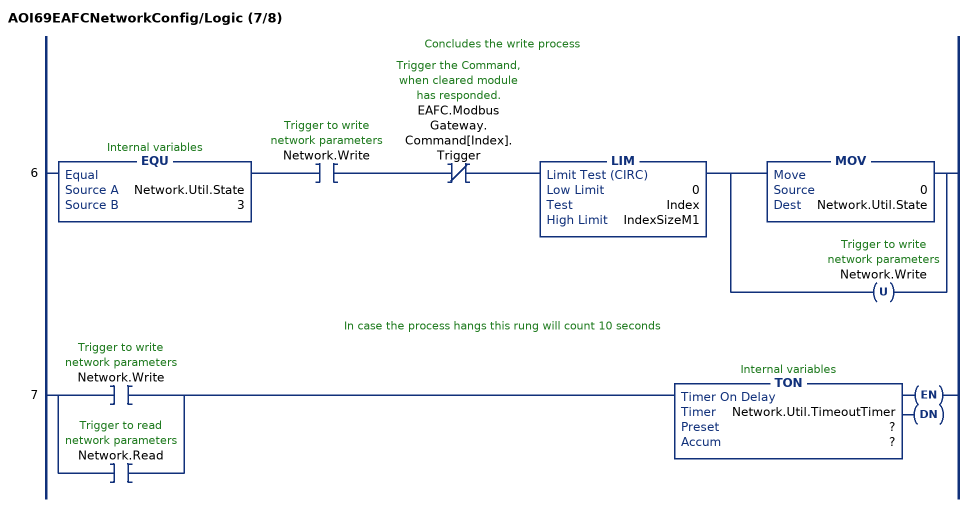
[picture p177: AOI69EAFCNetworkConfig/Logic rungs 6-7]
   // Concludes the write process
   6: EQU(Network.Util.State,3)XIC(Network.Write)XIO(EAFC.ModbusGateway.Command[Index].Trigger)LIM(0,Index,IndexSizeM1)[MOV(0,Network.Util.State) ,OTU(Network.Write) ];
   // In case the process hangs this rung will count 10 seconds
   7: [XIC(Network.Write) ,XIC(Network.Read) ]TON(Network.Util.TimeoutTimer,?,?);
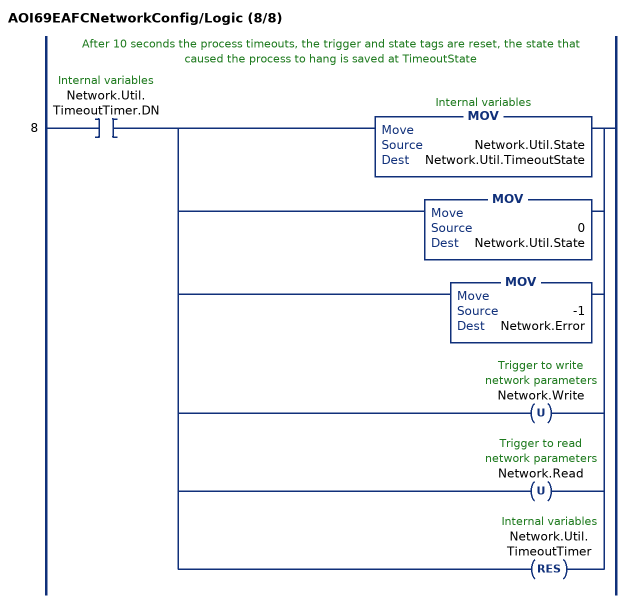
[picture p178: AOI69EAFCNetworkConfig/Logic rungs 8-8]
   // After 10 seconds the process timeouts, the trigger and state tags are reset, the state that caused the process to hang is saved at TimeoutState
   8: XIC(Network.Util.TimeoutTimer.DN)[MOV(Network.Util.State,Network.Util.TimeoutState) ,MOV(0,Network.Util.State) ,MOV(-1,Network.Error) ,OTU(Network.Write) ,OTU(Network.Read) ,RES(Network.Util.TimeoutTimer) ];
END_ROUTINE
